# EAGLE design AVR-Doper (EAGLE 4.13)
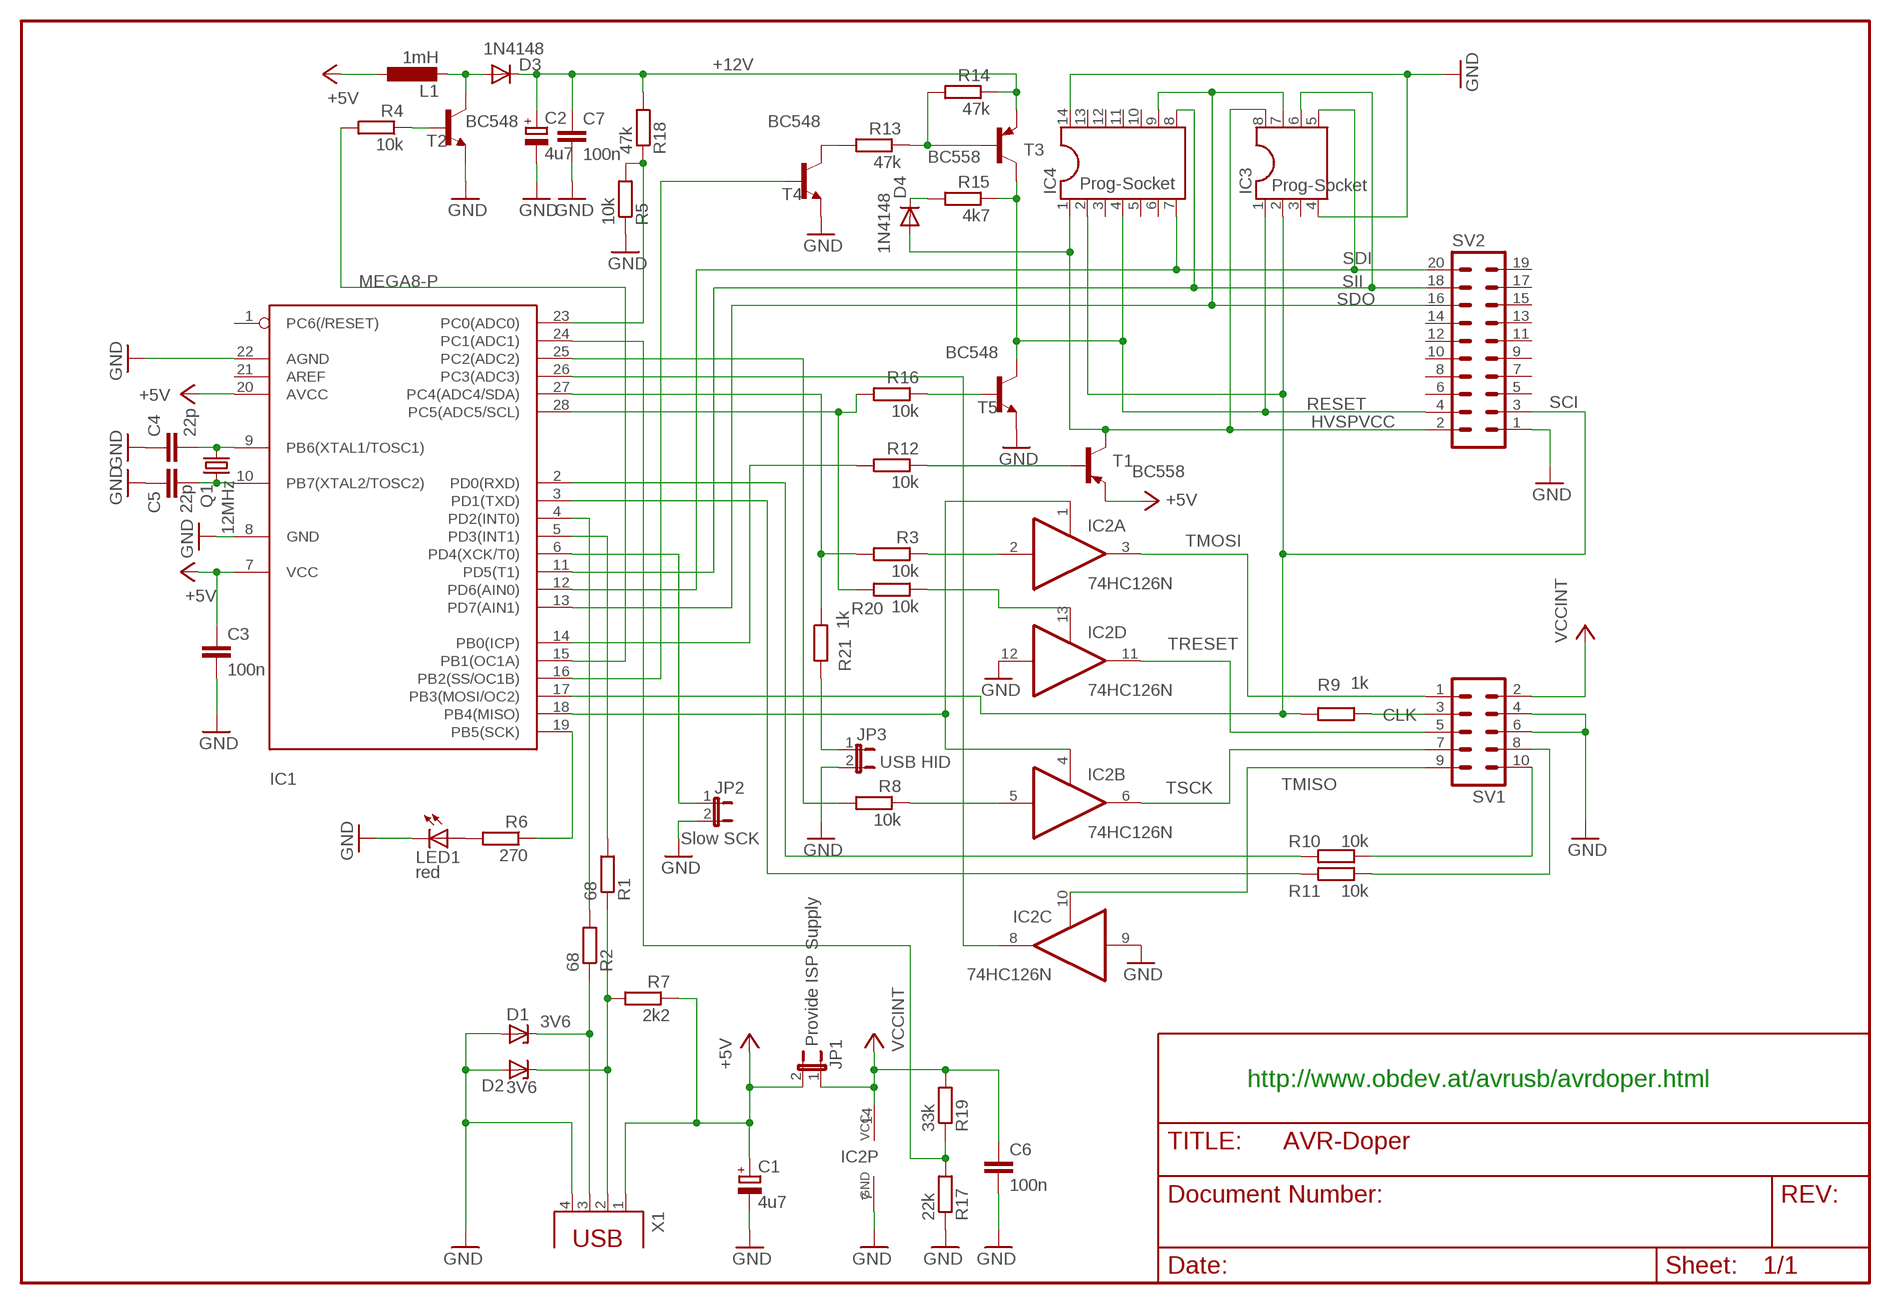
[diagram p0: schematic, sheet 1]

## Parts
C1  4u7  CPOL-EUE2.5-5  [E2,5-5]
C2  4u7  CPOL-EUE2.5-5  [E2,5-5]
C3  100n  C-EU025-024X044  [C025-024X044]
C4  22p  C-EU025-024X044  [C025-024X044]
C5  22p  C-EU025-024X044  [C025-024X044]
C6  100n  C-EU025-024X044  [C025-024X044]
C7  100n  C-EU025-024X044  [C025-024X044]
D1  3V6  ZENER-DIODEDO34-7  [DO34Z7]
D2  3V6  ZENER-DIODEDO34-7  [DO34Z7]
D3  1N4148  1N41487MM  [DO35-7]
D4  1N4148  1N41487MM  [DO35-7]
IC1  MEGA8-P  [DIL28-3]
IC2  74HC126N  [DIL14]
IC3  Prog-Socket  DIL8S  [SOCKED-08]
IC4  Prog-Socket  DIL14S  [SOCKED-14]
JP1  Provide ISP Supply  JP1E  [JP1]
JP2  Slow SCK  JP1E  [JP1]
JP3  USB HID  JP1E  [JP1]
L1  1mH  L-EU0207/12  [0207/12]
LED1  red  LED3MM  [LED3MM]
Q1  12MHz  CRYTALHC49S  [HC49/S]
R1  68  R-EU_0207/10  [0207/10]
R2  68  R-EU_0207/10  [0207/10]
R3  10k  R-EU_0207/10  [0207/10]
R4  10k  R-EU_0207/10  [0207/10]
R5  10k  R-EU_0207/10  [0207/10]
R6  270  R-EU_0207/10  [0207/10]
R7  2k2  R-EU_0207/10  [0207/10]
R8  10k  R-EU_0207/10  [0207/10]
R9  1k  R-EU_0207/10  [0207/10]
R10  10k  R-EU_0207/10  [0207/10]
R11  10k  R-EU_0207/10  [0207/10]
R12  10k  R-EU_0207/10  [0207/10]
R13  47k  R-EU_0207/10  [0207/10]
R14  47k  R-EU_0207/10  [0207/10]
R15  4k7  R-EU_0207/10  [0207/10]
R16  10k  R-EU_0207/10  [0207/10]
R17  22k  R-EU_0207/10  [0207/10]
R18  47k  R-EU_0207/10  [0207/10]
R19  33k  R-EU_0207/10  [0207/10]
R20  10k  R-EU_0207/10  [0207/10]
R21  1k  R-EU_0207/10  [0207/10]
SV1  ML10L  [ML10L]
SV2  ML20L  [ML20L]
T1  BC558  -PNP-TO92/  [TO92/]
T2  BC548  2N930-NPN-TO18-EBC  [TO18]
T3  BC558  -PNP-TO92/  [TO92/]
T4  BC548  2N930-NPN-TO18-EBC  [TO18]
T5  BC548  2N930-NPN-TO18-EBC  [TO18]
X1  PN61729  [PN61729]

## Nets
+5V: C1.+ C3.1 IC1.7(VCC) IC1.20(AVCC) JP1.2 L1.1 R7.1 T1.1(E) X1.1
+12V: C2.+ C7.1 D3.C R14.1 R18.2 T3.1(E)
CLK: R9.1 SV1.3
GND: C1.- C2.- C3.2 C4.1 C5.1 C6.2 C7.2 D1.A D2.A IC1.8(GND) IC1.22(AGND) IC2.7(P:GND) IC2.9(C:I) IC2.12(D:I) IC3.4 IC4.14 JP2.2 JP3.2 LED1.K(C) R5.1 R17.1 SV1.4 SV1.6 SV2.1 T2.1(E) T4.1(E) T5.1(E) X1.4
HVSPVCC: D4.A IC3.8 IC4.1 SV2.2 T1.3(C)
N$1: IC1.18(PB4(MISO)) IC2.1(A:OE) IC2.4(B:OE)
N$2: IC2.2(A:I) R3.1
N$3: IC2.5(B:I) R8.1
N$4: IC1.27(PC4(ADC4/SDA)) R3.2 R21.1
N$5: D2.C R1.1 R7.2 X1.2
N$6: IC1.25(PC2(ADC2)) R8.2
N$7: IC1.4(PD2(INT0)) R2.2
N$8: D1.C R2.1 X1.3
N$9: IC1.28(PC5(ADC5/SCL)) R16.2 R20.2
N$10: IC1.26(PC3(ADC3)) IC2.8(C:O)
N$11: IC1.24(PC1(ADC1)) R17.2 R19.1
N$12: R10.1 SV1.10
N$13: IC1.2(PD0(RXD)) R10.2
N$14: IC1.3(PD1(TXD)) R11.2
N$15: R11.1 SV1.8
N$18: R12.1 T1.2(B)
N$19: IC1.14(PB0(ICP)) R12.2
N$20: IC2.13(D:OE) R20.1
N$21: IC1.5(PD3(INT1)) R1.2
N$22: C4.2 IC1.9(PB6(XTAL1/TOSC1)) Q1.2
N$23: C5.2 IC1.10(PB7(XTAL2/TOSC2)) Q1.1
N$25: LED1.A R6.2
N$26: IC1.15(PB1(OC1A)) R4.2
N$27: D3.A L1.2 T2.3(C)
N$29: R4.1 T2.2(B)
N$30: R13.2 T4.3(C)
N$31: R13.1 R14.2 T3.2(B)
N$32: JP3.1 R21.2
N$33: IC1.23(PC0(ADC0)) R5.2 R18.1
N$34: D4.C R15.2
N$35: R16.1 T5.2(B)
N$37: IC1.16(PB2(SS/OC1B)) T4.2(B)
N$38: IC1.6(PD4(XCK/T0)) JP2.1
N$39: IC1.19(PB5(SCK)) R6.1
RESET: IC3.1 IC4.4 R15.1 SV2.4 T3.3(C) T5.3(C)
SCI: IC1.17(PB3(MOSI/OC2)) IC3.2 IC4.2 R9.2 SV2.3
SDI: IC1.12(PD6(AIN0)) IC3.5 IC4.7 SV2.20
SDO: IC1.13(PD7(AIN1)) IC3.7 IC4.9 SV2.16
SII: IC1.11(PD5(T1)) IC3.6 IC4.8 SV2.18
TMISO: IC2.10(C:OE) SV1.9
TMOSI: IC2.3(A:O) SV1.1
TRESET: IC2.11(D:O) SV1.5
TSCK: IC2.6(B:O) SV1.7
VCCINT: C6.1 IC2.14(P:VCC) JP1.1 R19.2 SV1.2
Unconnected: IC1.1(PC6(/RESET)) IC1.21(AREF) IC3.3 IC4.3 IC4.5 IC4.6 IC4.10 IC4.11 IC4.12 IC4.13 SV2.5 SV2.6 SV2.7 SV2.8 SV2.9 SV2.10 SV2.11 SV2.12 SV2.13 SV2.14 SV2.15 SV2.17 SV2.19

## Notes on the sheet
- http://www.obdev.at/avrusb/avrdoper.html

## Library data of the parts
C1 C2 = rcl:CPOL-EU: POLARIZED CAPACITOR, European symbol
C3-C7 = rcl:C-EU: CAPACITOR, European symbol
D1 D2 = diode:ZENER-DIODE: Z-Diode
D3 D4 = diode:1N4148: DIODE
IC1 = atmel:MEGA8-P: MICROCONTROLLER 8 Kbytes FLASH 1 kbytes SRAM 512 bytes EEPROM USART 4-channel 10 bit ADC 2-channel 8 bit ADC Source: avr.lbr
IC2 = 74xx-eu:74*126: Quad bus BUFFER, 3-state
IC3 = ic-package:DIL8: Dual In Line
IC4 = ic-package:DIL14: Dual In Line
JP1-JP3 = jumper:JP1E: JUMPER
L1 = rcl:L-EU: INDUCTOR, European symbol
LED1 = led:LED: LED
Q1 = crystal:CRYTAL: CRYSTAL
R1-R21 = rcl:R-EU_: RESISTOR, European symbol
SV1 = con-harting-ml:ML10: HARTING
SV2 = con-harting-ml:ML20: HARTING
T1 T3 = transistor:*-PNP-: PNP Transistror
T2 T4 T5 = transistor:*-NPN-: NPN Transistror
X1 = con-berg:PN61729: BERG USB connector

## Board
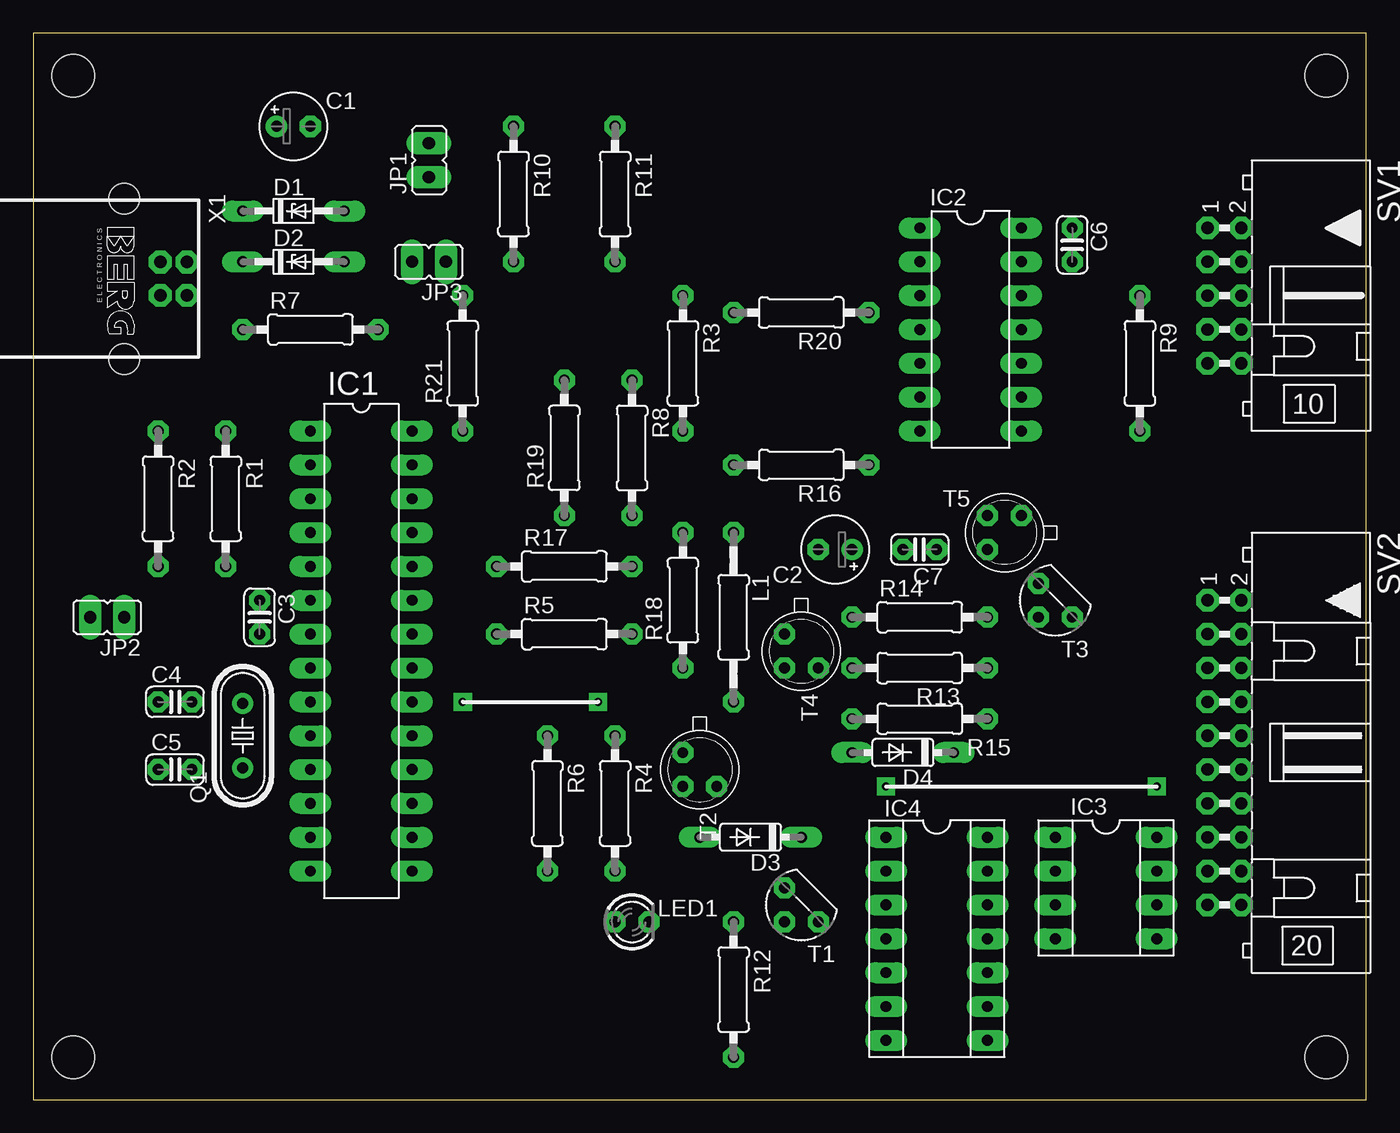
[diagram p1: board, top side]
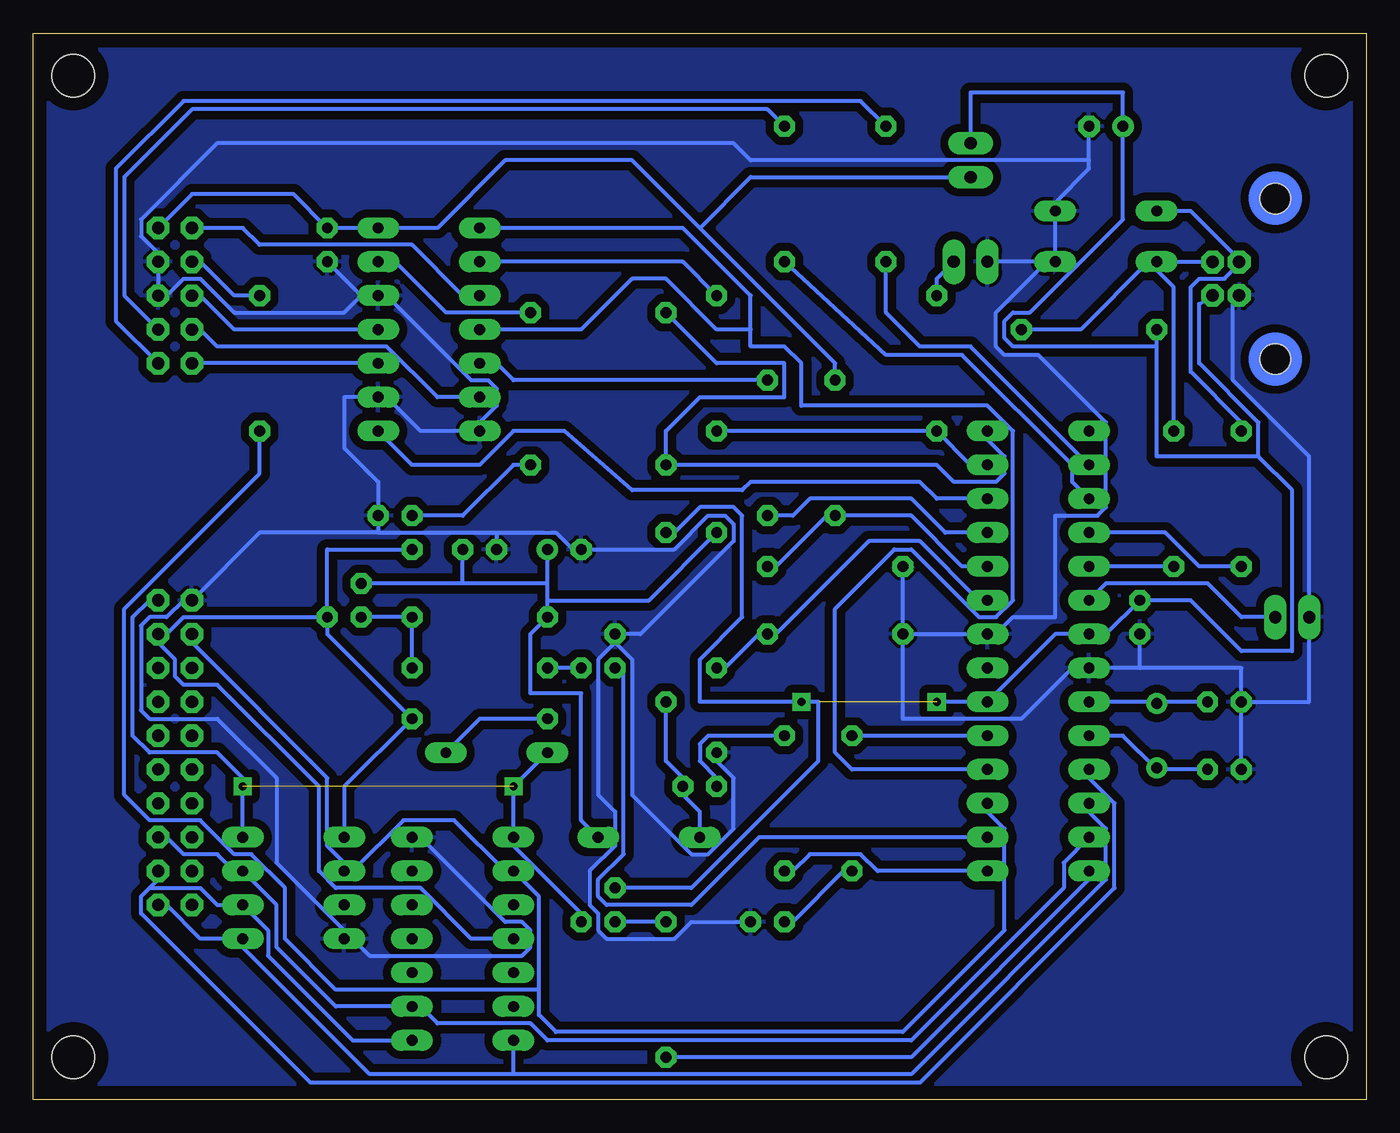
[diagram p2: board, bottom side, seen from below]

Size 100 x 80 mm. Coordinates in mm from the lower left corner, seen from the top.
Outline: 0,0 100,0 100,80 0,80 0,0
Copper layers 16: Bottom 0.035mm
Design rules "default": minimum track width 12mil, minimum drill 31mil, track to track 8mil, track to pad 8mil, pad to pad 8mil, via to via 8mil, smd to smd 8mil, copper to edge 40mil, drill to drill 8mil, minimum pad ring 15mil, minimum via ring 15mil, stop-mask expansion 4mil, vias tented up to drill 0mil, thermal gap 10mil
Holes 3.2 mm at 3.01,76.83 3.01,3.17 96.99,3.17 96.99,76.83

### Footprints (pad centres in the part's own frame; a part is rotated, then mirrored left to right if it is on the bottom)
E2,5-5 = drill 0.813 pad 1.6 round: + -1.27,0 | drill 0.813 pad 1.6 octagon: - 1.27,0
C025-024X044 = drill 0.813 octagon: 1 -1.27,0; 2 1.27,0
DO34Z7 = drill 0.813 long: A 3.81,0; C -3.81,0
DO35-7 = drill 0.813 long: A 3.81,0; C -3.81,0
DIL28-3 = drill 0.813 long: 1 -16.51,-3.81; 2 -13.97,-3.81; 3 -11.43,-3.81; 4 -8.89,-3.81; 5 -6.35,-3.81; 6 -3.81,-3.81; 7 -1.27,-3.81; 8 1.27,-3.81; 9 3.81,-3.81; 10 6.35,-3.81; 11 8.89,-3.81; 12 11.43,-3.81; 13 13.97,-3.81; 14 16.51,-3.81; 15 16.51,3.81; 16 13.97,3.81; 17 11.43,3.81; 18 8.89,3.81; 19 6.35,3.81; 20 3.81,3.81; 21 1.27,3.81; 22 -1.27,3.81; 23 -3.81,3.81; 24 -6.35,3.81; 25 -8.89,3.81; 26 -11.43,3.81; 27 -13.97,3.81; 28 -16.51,3.81
DIL14 = drill 0.813 long: 1 -7.62,-3.81; 2 -5.08,-3.81; 3 -2.54,-3.81; 4 0,-3.81; 5 2.54,-3.81; 6 5.08,-3.81; 7 7.62,-3.81; 8 7.62,3.81; 9 5.08,3.81; 10 2.54,3.81; 11 0,3.81; 12 -2.54,3.81; 13 -5.08,3.81; 14 -7.62,3.81
SOCKED-08 = drill 0.813 long: 1 -3.81,-3.81; 2 -1.27,-3.81; 3 1.27,-3.81; 4 3.81,-3.81; 5 3.81,3.81; 6 1.27,3.81; 7 -1.27,3.81; 8 -3.81,3.81
SOCKED-14 = drill 0.813 long: 1 -7.62,-3.81; 2 -5.08,-3.81; 3 -2.54,-3.81; 4 0,-3.81; 5 2.54,-3.81; 6 5.08,-3.81; 7 7.62,-3.81; 8 7.62,3.81; 9 5.08,3.81; 10 2.54,3.81; 11 0,3.81; 12 -2.54,3.81; 13 -5.08,3.81; 14 -7.62,3.81
JP1 = drill 0.914 long: 1 0,-1.27; 2 0,1.27
0207/12 = drill 0.813 octagon: 1 -6.35,0; 2 6.35,0
LED3MM = drill 0.813 octagon: A -1.27,0; K 1.27,0
HC49/S = drill 0.813 round: 1 -2.413,0; 2 2.413,0
0207/10 = drill 0.813 octagon: 1 -5.08,0; 2 5.08,0
ML10L = drill 0.914 octagon: 1 -5.08,-1.27; 2 -5.08,1.27; 3 -2.54,-1.27; 4 -2.54,1.27; 5 0,-1.27; 6 0,1.27; 7 2.54,-1.27; 8 2.54,1.27; 9 5.08,-1.27; 10 5.08,1.27
ML20L = drill 0.914 octagon: 1 -11.43,-1.27; 2 -11.43,1.27; 3 -8.89,-1.27; 4 -8.89,1.27; 5 -6.35,-1.27; 6 -6.35,1.27; 7 -3.81,-1.27; 8 -3.81,1.27; 9 -1.27,-1.27; 10 -1.27,1.27; 11 1.27,-1.27; 12 1.27,1.27; 13 3.81,-1.27; 14 3.81,1.27; 15 6.35,-1.27; 16 6.35,1.27; 17 8.89,-1.27; 18 8.89,1.27; 19 11.43,-1.27; 20 11.43,1.27
TO92/ = drill 0.813 octagon: 1 1.27,-1.27; 2 1.27,1.27; 3 -1.27,1.27
TO18 = drill 0.813 octagon: 1 -1.27,-1.27; 2 1.27,-1.27; 3 1.27,1.27
PN61729 = drill 0.95 octagon: 1 1.25,4.71; 2 -1.25,4.71; 3 -1.25,2.71; 4 1.25,2.71 | hole 2.3: -6.02,0; 6.02,0

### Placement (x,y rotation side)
C1  19.52,73.02 0 top
C2  60.16,41.27 180 top
C3  16.98,36.19 270 top
C4  10.63,29.84 0 top
C5  10.63,24.76 0 top
C6  77.94,64.13 270 top
C7  66.51,41.27 180 top
D1  19.52,66.67 0 top
D2  19.52,62.86 0 top
D3  53.81,19.68 180 top
D4  65.24,26.03 180 top
IC1  24.6,33.65 270 top
IC2  70.32,57.78 270 top
IC3  80.48,15.87 270 top
IC4  67.78,12.06 270 top
JP1  29.68,70.48 0 top
JP2  5.55,36.19 90 top
JP3  29.68,62.86 90 top
L1  52.54,36.19 270 top
LED1  44.92,13.33 0 top
Q1  15.71,27.3 90 top
R1  14.44,45.08 270 top
R2  9.36,45.08 270 top
R3  48.73,55.24 270 top
R4  43.65,22.22 270 top
R5  39.84,34.92 0 top
R6  38.57,22.22 270 top
R7  20.79,57.78 0 top
R8  44.92,48.89 270 top
R9  83.02,55.24 270 top
R10  36.03,67.94 270 top
R11  43.65,67.94 270 top
R12  52.54,8.25 270 top
R13  66.51,32.38 180 top
R14  66.51,36.19 0 top
R15  66.51,28.57 180 top
R16  57.62,47.62 180 top
R17  39.84,40 0 top
R18  48.73,37.46 90 top
R19  39.84,48.89 90 top
R20  57.62,59.05 180 top
R21  32.22,55.24 90 top
SV1  89.37,60.32 270 top
SV2  89.37,26.03 270 top
T1  57.62,14.6 180 top
T2  50,24.76 270 top
T3  76.67,37.46 180 top
T4  57.62,33.65 270 top
T5  72.86,42.54 180 top
X1  6.82,61.59 270 top

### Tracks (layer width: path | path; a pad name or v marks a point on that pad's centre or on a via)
+5V  (via drill 0.6)  (1 unrouted)
  Bottom 0.305: T1.1 50.63,15.87 41.11,25.39 41.11,29.84 v42.38,29.84 50,29.84 50,33.02 46.82,36.19 46.82,43.81 47.46,44.45 50,44.45 51.91,42.54 L1.1 | 15.71,56.51 15.71,48.26 8.09,48.26 | 15.71,56.51 26.5,56.51 27.14,57.15 27.14,58.41 26.5,59.05 25.23,59.05 18.25,66.03 C1.+ 18.25,75.56 29.68,75.56 JP1.2 | X1.1 12.54,59.69 12.54,55.24 8.09,50.8 8.09,48.26 | 8.09,48.26 5.55,45.72 5.55,33.65 9.36,33.65 13.17,37.46 C3.1 19.52,34.92 IC1.7 23.33,34.92 IC1.20 32.22,29.84 | 15.71,56.51 R7.1
+12V
  Bottom 0.305: R18.2 53.81,37.46 61.43,37.46 | 61.43,37.46 R14.1 62.7,34.92 62.7,30.47 58.89,30.47 58.89,20.95 D3.C | 61.43,37.46 61.43,38.73 | 61.43,38.73 C2.+ | 61.43,38.73 67.78,38.73 | 67.78,38.73 T3.1 | 67.78,38.73 C7.1
CLK
  Bottom 0.305: R9.1 84.92,60.32 87.47,62.86 SV1.3
GND
  Bottom 0.305: R5.1 IC1.22 27.77,34.92 26.5,36.19 23.33,36.19 23.33,43.81 20.15,43.81 19.52,44.45 19.52,50.8 24.6,55.88 27.14,55.88 27.77,56.51 27.77,59.05 23.96,62.86 D2.A | R5.1 R17.1 | D2.A D1.A 23.33,67.3 20.79,69.84 20.79,70.48 | 20.79,70.48 C1.- | C5.1 C4.1 | C4.1 9.36,32.38 16.98,32.38 | 16.98,32.38 IC1.8 22.06,32.38 25.87,28.57 34.76,28.57 R5.1 | X1.4 10,59.69 10,53.97 4.28,48.26 JP2.2 4.28,29.84 C4.1 | 56.35,34.29 57.62,33.02 57.62,22.86 56.35,21.58 56.35,19.04 58.25,17.14 58.25,14.6 57.62,13.97 57.62,12.7 56.98,12.06 51.91,12.06 50.63,13.33 LED1.K | 56.35,34.29 55.08,33.02 55.08,22.86 50.63,18.41 49.37,18.41 47.46,20.31 47.46,24.12 48.73,25.39 T2.1 | 56.35,34.29 T4.1 54.45,34.92 47.46,41.91 47.46,43.18 48.09,43.81 49.37,43.81 51.91,41.27 C2.- 59.52,41.27 60.8,42.54 65.24,42.54 | IC4.14 70.95,19.68 64.61,13.33 63.34,13.33 62.7,12.7 62.7,11.43 63.34,10.79 74.77,10.79 76.03,12.06 IC3.4 76.67,12.7 81.75,17.77 81.75,24.12 86.19,28.57 91.28,28.57 91.91,29.2 91.91,35.55 91.28,36.19 90,36.19 88.73,37.46 SV2.1 83.02,42.54 74.13,42.54 | 74.13,42.54 65.24,42.54 | 74.13,42.54 T5.1 74.13,46.35 76.67,48.89 76.67,52.7 IC2.9 73.5,52.7 70.95,50.16 IC2.7 66.51,50.8 65.24,52.07 65.24,53.34 65.88,53.97 67.14,53.97 73.5,60.32 IC2.12 75.4,60.32 | 20.79,70.48 46.19,70.48 47.46,71.75 86.19,71.75 91.91,66.03 91.91,64.77 90.64,63.5 SV1.4 SV1.6 90,60.32 88.73,61.59 87.47,61.59 84.92,59.05 76.67,59.05 75.4,60.32 | 75.4,60.32 C6.2 | 16.98,32.38 C3.2 | 65.24,42.54 C7.2 | D2.A JP3.2
  pour Bottom (isolate 0.61): 0.47,79.37 99.53,79.37 99.53,0.63 0.47,0.63
HVSPVCC  (via drill 0.6)  (1 unrouted)
  Bottom 0.305: T1.3 58.89,13.97 63.97,19.04 IC4.1 63.97,23.49 D4.A | IC3.8 v84.29,23.49 84.29,24.12 86.19,26.03 91.28,26.03 92.55,27.3 92.55,36.19 91.28,37.46 SV2.2
N$1
  Bottom 0.305: 65.88,57.78 IC2.4 58.89,57.78 55.08,61.59 52.54,61.59 48.73,57.78 46.19,57.78 | IC2.1 51.27,65.4 46.19,60.32 46.19,57.78 | 46.19,57.78 46.19,56.51 43.65,56.51 42.38,55.24 42.38,52.07 28.41,52.07 26.5,50.16 26.5,37.46 27.77,36.19 29.04,36.19 34.12,41.27 35.39,41.27 39.84,36.83 39.84,26.03 38.57,24.76 IC1.18
N$2
  Bottom 0.305: R3.1 51.27,62.86 IC2.2
N$3
  Bottom 0.305: R8.1 63.97,53.97 65.24,55.24 IC2.5
N$4
  Bottom 0.305: IC1.27 29.68,47.62 R21.1 R3.2
N$5
  Bottom 0.305: R1.1 14.44,60.96 15.71,62.23 D2.C | R7.2 21.42,57.78 16.34,62.86 D2.C | X1.2 11.9,62.86 D2.C
N$6
  Bottom 0.305: IC1.25 31.58,42.54 34.12,45.08 41.74,45.08 43.02,43.81 R8.2
N$7
  Bottom 0.305: R2.2 12.54,40 15.08,42.54 IC1.4
N$8
  Bottom 0.305: R2.1 9.36,50.8 13.17,54.61 13.17,60.96 12.54,61.59 10.63,61.59 10,62.23 X1.3 10,63.5 13.17,66.67 D1.C
N$9
  Bottom 0.305: IC1.28 28.41,49.53 27.14,48.26 27.14,46.98 27.77,46.35 30.95,46.35 32.22,47.62 R16.2 52.54,50.16 50,52.7 43.65,52.7 43.65,55.24 48.73,55.24 R20.2
N$10
  Bottom 0.305: IC1.26 32.22,45.08 33.49,46.35 46.19,46.35 46.82,45.72 55.08,45.72 60.16,50.16 63.97,50.16 66.51,47.62 71.59,47.62 IC2.8
N$11
  Bottom 0.305: IC1.24 30.31,40 34.12,43.81 R19.1 40.48,43.81 44.28,40 R17.2
N$12
  Bottom 0.305: R10.1 37.94,74.92 88.73,74.92 93.81,69.84 93.81,58.41 SV1.10
N$13
  Bottom 0.305: IC1.2 29.68,56.51 33.49,56.51 36.03,59.05 R10.2
N$14
  Bottom 0.305: IC1.3 22.06,46.35 22.06,47.62 30.31,55.88 36.03,55.88 R11.2
N$15
  Bottom 0.305: R11.1 44.92,74.29 88.1,74.29 93.18,69.21 93.18,60.32 SV1.8
N$17  (via drill 0.6)
  other vias: 32.22,29.84
N$18
  Bottom 0.305: R12.1 T1.2
N$19
  Bottom 0.305: R12.2 34.12,3.17 20.79,16.5 IC1.14
N$20
  Bottom 0.305: R20.1 69.05,59.05 72.86,62.86
  Bottom 0.406: 72.86,62.86 IC2.13
N$21
  Bottom 0.305: R1.2 IC1.5
N$22
  Bottom 0.305: C4.2 15.08,29.84 Q1.2 16.34,29.84 IC1.9
N$23
  Bottom 0.305: IC1.10 18.25,27.3 15.71,24.76 | 15.71,24.76 Q1.1 | C5.2 15.71,24.76
N$24  (via drill 0.6)
  other vias: 63.97,23.49
N$25
  Bottom 0.305: R6.2 39.2,17.14 43.02,13.33 LED1.A
N$26
  Bottom 0.305: IC1.15 36.66,17.14 37.94,18.41 41.74,18.41 43.02,17.14 R4.2
N$27
  Bottom 0.305: D3.A 50,21.58 51.27,22.86 T2.3 51.27,24.12 52.54,25.39 L1.2
N$28
  pour Bottom (isolate 0.61): 0.47,79.37 99.53,79.37 99.53,0.63 0.47,0.63
N$29
  Bottom 0.305: R4.1 49.37,27.3 50,26.66 50,25.39 48.73,24.12 T2.2
N$30
  Bottom 0.305: T4.3 R13.2
N$31
  Bottom 0.305: R13.1 R14.2 T3.2
N$32
  Bottom 0.305: R21.2 32.22,61.59 JP3.1
N$33
  Bottom 0.305: IC1.23 29.04,37.46 33.49,41.91 37.3,41.91 44.28,34.92 R5.2 45.55,34.92 48.09,32.38 R18.1
N$34
  Bottom 0.305: R15.2 66.51,28.57 D4.C
N$35
  Bottom 0.305: T5.2 67.78,43.81 63.97,47.62 R16.1
N$37
  Bottom 0.305: IC1.16 45.55,19.68 50.63,14.6 56.98,14.6 57.62,15.24 57.62,16.5 55.71,18.41 55.71,32.38 T4.2
N$38
  Bottom 0.305: IC1.6 19.52,38.73 11.9,38.73 9.36,36.19 JP2.1
N$39
  Bottom 0.305: IC1.19 R6.1
RESET
  Bottom 0.305: IC4.4 67.14,12.06 70.95,15.87 77.3,15.87 78.58,17.14 78.58,23.49 86.19,31.11 88.73,31.11 89.37,31.74 89.37,33.02 90.64,34.29 SV2.4 90,34.92 88.73,36.19 T3.3 | T5.3 77.94,41.27 T3.3 | T3.3 77.94,34.92 R15.1 76.67,23.49 IC3.1
SCI
  Bottom 0.305: 62.06,8.25 62.06,6.34 60.8,5.08 34.76,5.08 27.14,12.7 27.14,20.31 28.41,21.58 IC1.17 | 62.06,8.25 77.3,8.25 81.11,12.06 81.11,15.87 83.66,18.41 84.92,18.41 87.47,20.95 91.28,20.95 93.18,22.86 93.18,36.83 83.02,46.98 R9.2 | 62.06,8.25 62.06,15.24 IC4.2 64.61,17.14 68.41,20.95 72.22,20.95 76.03,17.14 IC3.2 76.67,17.77 77.94,19.04 77.94,24.12 88.1,34.29 SV2.3
SDI
  Bottom 0.305: SV2.20 90,14.6 87.47,12.06 IC3.5 84.29,11.43 74.77,1.9 63.97,1.9 | 63.97,1.9 34.12,1.9 19.52,16.5 19.52,20.31 20.79,21.58 IC1.12 | 63.97,1.9 IC4.7
SDO
  Bottom 0.305: IC1.13 22.7,17.77 22.7,15.87 34.12,4.44 61.43,4.44 62.7,5.71 69.69,5.71 70.95,6.98 IC4.9 77.3,6.98 81.75,11.43 81.75,14.6 IC3.7 84.92,17.14 86.19,18.41 88.73,18.41 90,19.68 SV2.16
SII
  Bottom 0.305: IC4.8 76.03,4.44 82.39,10.79 82.39,12.7 IC3.6 86.19,14.6 87.47,15.87 91.28,15.87 | 91.28,15.87 90.64,16.5 SV2.18 | 91.28,15.87 91.91,15.24 91.91,13.97 79.21,1.27 33.49,1.27 18.88,15.87 18.88,22.22 20.79,24.12 IC1.11
TMISO
  Bottom 0.305: IC2.10 SV1.9
TMOSI
  Bottom 0.305: IC2.3 67.78,60.32 71.59,64.13 83.02,64.13 84.29,65.4 SV1.1
TRESET
  Bottom 0.305: IC2.11 84.92,57.78 87.47,60.32 SV1.5
TSCK
  Bottom 0.305: IC2.6 69.69,52.7 73.5,56.51 86.19,56.51 87.47,57.78 SV1.7
VCCINT
  Bottom 0.305: 50,65.4 39.84,55.24 R19.2 | 50,65.4 55.08,70.48 64.61,70.48 69.69,65.4 IC2.14 C6.1 80.48,67.94 88.1,67.94 SV1.2 | JP1.1 46.19,69.21 50,65.4
(copper drawn outside any net)
  shapes: Bottom circle x2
